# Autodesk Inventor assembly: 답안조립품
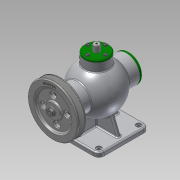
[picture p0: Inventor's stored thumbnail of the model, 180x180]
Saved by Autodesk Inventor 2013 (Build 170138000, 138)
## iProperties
Created: 2018-06
Part Number: 답안조립품
Document SubType Name: Assembly
Designer: Administrator
Author: Administrator
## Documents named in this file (19)
- C:\Users\Administrator\Desktop\480612V1009\답안조립품.iam
- C:\Users\Administrator\Desktop\480612V1009\본체.ipt
- C:\Users\Administrator\Desktop\480612V1009\V-벨트풀리.ipt
- C:\Users\Administrator\Desktop\480612V1009\너트 M8.ipt
- C:\Users\Administrator\Desktop\480612V1009\뒤커버.ipt
- C:\Users\Administrator\Desktop\480612V1009\멈춤링 15x1.ipt
- C:\Users\Administrator\Desktop\480612V1009\멈춤링 35x1.6.ipt
- 멈춤링 35x1.6.ipt
- C:\Users\Administrator\Desktop\480612V1009\베어링 6202.ipt
- 베어링 6202.ipt
- C:\Users\Administrator\Desktop\480612V1009\볼트 M4x12.ipt
- C:\Users\Administrator\Desktop\480612V1009\볼트 M4x16.ipt
- C:\Users\Administrator\Desktop\480612V1009\부시.ipt
- C:\Users\Administrator\Desktop\480612V1009\상부커버.ipt
- C:\Users\Administrator\Desktop\480612V1009\슬라이드.ipt
- C:\Users\Administrator\Desktop\480612V1009\앞커버.ipt
- C:\Users\Administrator\Desktop\480612V1009\오일 실 15 30 7.ipt
- C:\Users\Administrator\Desktop\480612V1009\키 4x4x12.ipt
- C:\Users\Administrator\Desktop\480612V1009\편심축.ipt
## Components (1 placed, 1 different names)
1. V-벨트풀리:1
